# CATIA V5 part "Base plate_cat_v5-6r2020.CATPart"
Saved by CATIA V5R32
Part number: Base Plate
Bounding box of the stored display mesh (mm): x -10 to 10, y 0 to 144, z 0 to 6
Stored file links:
  D:\PROJECTS\Project 2022\CATIA V5 6R 2022\Resources\Tutorial Files\c13_catia_v5_6r2022_tut\c13tut2\Bench vice\Base plate_cat_v5-6r2020.CATPart
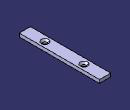
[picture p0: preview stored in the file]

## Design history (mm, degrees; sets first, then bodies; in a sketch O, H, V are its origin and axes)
Body1 (main body)
  Sketch1 on zx-plane, origin (0, 0, 0), H (-1, 0, 0), V (0, 0, 1)
    point P1 (-10, 0)
    line L1 (-10, 0) -> (10, 0)
    line L2 (10, 0) -> (10, 6)
    line L3 (10, 6) -> (-10, 6)
    line L4 (-10, 6) -> (-10, 0)
    length L3 = 20
    length L2 = 6
    distance V L2 = 10
    coincidence: P1 H
    horizontal: L1 H, L3 H
    vertical: L2 V, L4 V
  Pad1: profile Sketch1, direction (0, 1, 0), length 144
  Sketch2 on face of Pad1, origin (-6.0071, 115.251, 6), H (1, 0, 0), V (0, 1, 0)
    point P1 (6.0071, -9.251)
    reference projected line E1 (-3.9929, -115.251) -> (-3.9929, 28.749) from edge of Pad1
    reference projected line E2 (16.0071, 28.749) -> (-3.9929, 28.749) from edge of Pad1
    distance E1 P1 = 10
    distance E2 P1 = 38
  Hole1: placed by Sketch2, at (0, 106, 6) direction (0, 0, -1), diameter 7, through (limit type 6), countersink depth 3, countersink angle 90
  RectPattern1: of Hole1, direction 1 instances 2, spacing 70, along edge of Pad1 reversed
